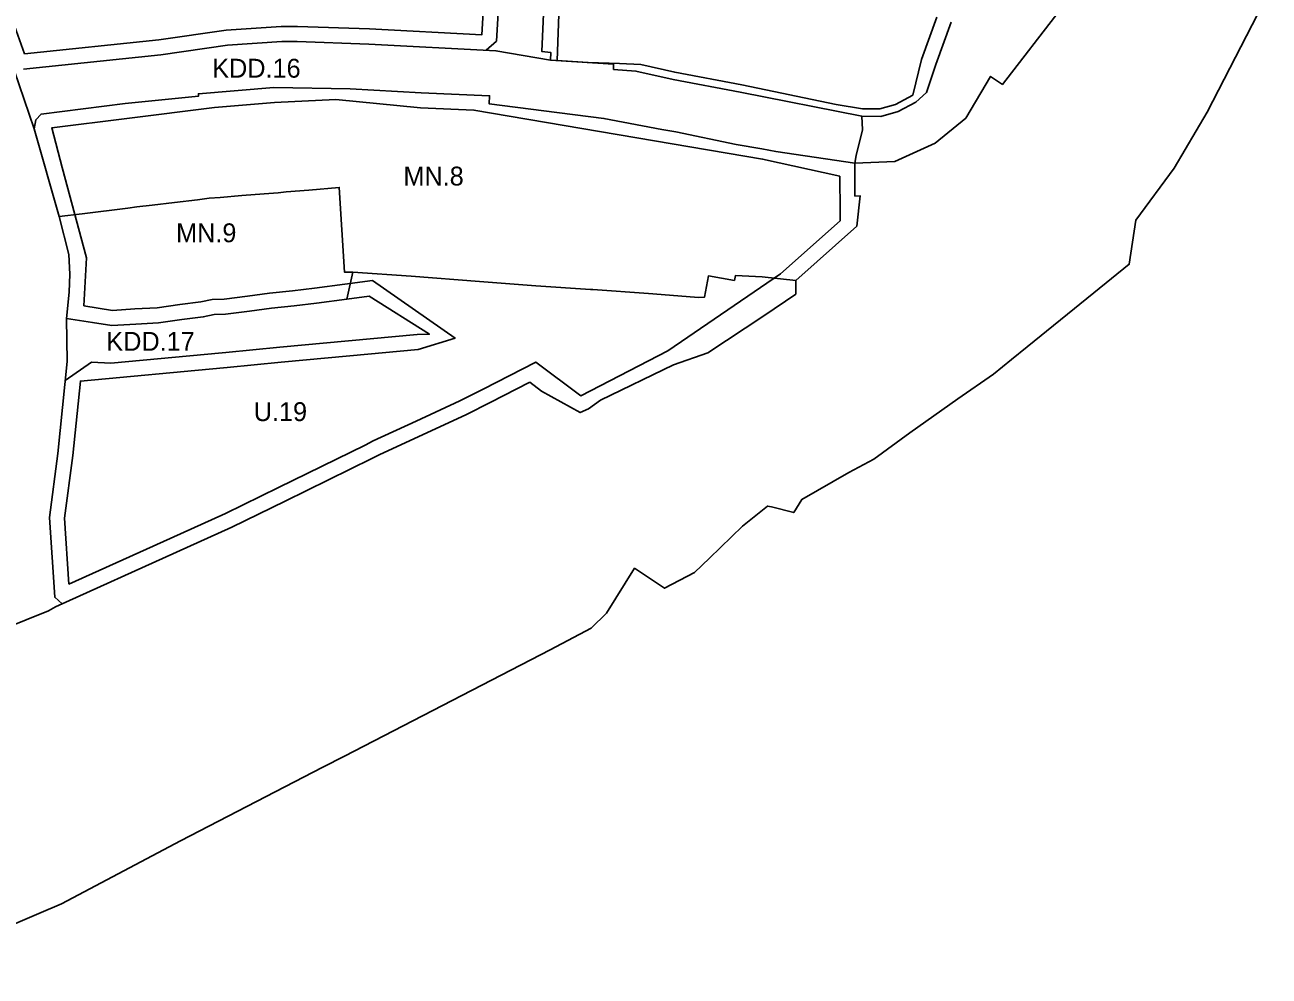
# Model space of a CAD drawing. Extents: x 7428112 to 7429828, y 5548245 to 5549272.
# Drawn here: x 7429274.1 to 7429603.6, y 5548527.3 to 5548779.3 of the extents above; entities that cross this region are included whole.
import ezdxf

# ---------------------------------------------------------------- set-up
doc = ezdxf.new("R2010")
doc.units = 0
for name, color, linetype in [('LIN_granica_planu', 7, 'Continuous'), ('LIN_Linia Zabudowy Nieprzekraczalna', 7, 'Continuous'), ('LIN_linie_rozgraniczajace', 7, 'Continuous'), ('TXT_oznaczenia_przeznaczen', 7, 'Continuous')]:
    doc.layers.add(name, color=color, linetype=linetype)

msp = doc.modelspace()

# ---------------------------------------------------------------- linework, layer by layer
at = {"layer": 'LIN_granica_planu'}
msp.add_lwpolyline([(7429603.57, 5548788.13), (7429587.19, 5548756.2), (7429578.44, 5548741.37), (7429568.31, 5548727.53), (7429566.55, 5548715.89), (7429557.13, 5548708.28), (7429539.53, 5548694.02), (7429535.37, 5548690.64), (7429530.55, 5548686.75), (7429521.17, 5548680.28), (7429508.44, 5548671.21), (7429498.89, 5548664.28), (7429492.28, 5548660.74), (7429479.85, 5548653.6), (7429477.69, 5548650.08), (7429471.8, 5548651.58), (7429470.74, 5548651.84), (7429464.08, 5548646.5), (7429455.39, 5548637.98), (7429451.43, 5548634.24), (7429443.49, 5548630.06), (7429435.54, 5548635.33), (7429428.09, 5548623.47), (7429424.02, 5548619.52), (7429413.15, 5548613.7), (7429358.69, 5548585.55), (7429353, 5548582.61), (7429315.25, 5548563.12), (7429315.25, 5548563.12), (7429283.8, 5548546.45), (7429277.79, 5548543.89), (7429238.95, 5548527.29)], dxfattribs=at)
at = {"layer": 'LIN_Linia Zabudowy Nieprzekraczalna'}
for points in [[(7429273.99, 5548771.63), (7429309.58, 5548775.34), (7429327.36, 5548777.91), (7429341.97, 5548778.88), (7429346.25, 5548778.91), (7429365.33, 5548778.23), (7429395.07, 5548776.65), (7429395.94, 5548791.78), (7429396.25, 5548798.38), (7429396.88, 5548810.65), (7429398.13, 5548829.54), (7429398.89, 5548843.94), (7429359.73, 5548846.77), (7429348.57, 5548847.59), (7429341.93, 5548845.59), (7429332.58, 5548841.75), (7429312.81, 5548833.85), (7429290.54, 5548825.46), (7429258.77, 5548813.12), (7429269.98, 5548782.77), (7429273.99, 5548771.63)], [(7429415.84, 5548791.95), (7429415.06, 5548769.88), (7429423.24, 5548769.35), (7429431.55, 5548769.1), (7429437.18, 5548768.82), (7429446.17, 5548766.76), (7429463.91, 5548763.41), (7429488.93, 5548758.22), (7429495.89, 5548757.09), (7429500.46, 5548757.03), (7429504.59, 5548758.22), (7429509.22, 5548760.7), (7429511.55, 5548770.13), (7429515.58, 5548781.39)], [(7429285.76, 5548631.12), (7429312.55, 5548643.25), (7429327.21, 5548649.89), (7429341.22, 5548656.74), (7429364.19, 5548668), (7429366.28, 5548669.1), (7429377.69, 5548674.35), (7429389.27, 5548679.68), (7429395.47, 5548682.8), (7429409.36, 5548689.98), (7429421.33, 5548681.06), (7429444.35, 5548692.92), (7429474.19, 5548713.38), (7429489.94, 5548727.43), (7429489.94, 5548729.85), (7429489.85, 5548739.22), (7429469.45, 5548743.75), (7429393.01, 5548756.72), (7429378.85, 5548757.31), (7429356.46, 5548759.58), (7429340.17, 5548758.73), (7429324.3, 5548757.39), (7429301.11, 5548754.53), (7429281.21, 5548752.02), (7429283.92, 5548741.49), (7429290.38, 5548717.55), (7429289.71, 5548704.91), (7429297.31, 5548703.65), (7429303.2, 5548704.04), (7429309.08, 5548704.38), (7429315.1, 5548705.2), (7429320.65, 5548705.9), (7429323.69, 5548706.54), (7429326.87, 5548706.66), (7429333.04, 5548707.41), (7429338.9, 5548708.21), (7429344.94, 5548708.83), (7429350.82, 5548709.56), (7429358.81, 5548710.64), (7429366.16, 5548711.56), (7429388.01, 5548696.33), (7429378.19, 5548693.29), (7429360.15, 5548691.63), (7429341.98, 5548689.95), (7429327.65, 5548688.53), (7429326.69, 5548688.44), (7429288.8, 5548684.95), (7429286.81, 5548665.25), (7429284.58, 5548648.66), (7429285.76, 5548631.12)]]:
    msp.add_lwpolyline(points, dxfattribs=at)
at = {"layer": 'LIN_linie_rozgraniczajace'}
for points in [[(7429399.93, 5548791.57), (7429398.98, 5548775.04), (7429396.26, 5548772.58)], [(7429413.24, 5548769.99), (7429413.33, 5548772.01), (7429410.96, 5548772.3), (7429411.85, 5548792.19)], [(7429238.95, 5548527.29), (7429277.79, 5548543.89), (7429283.8, 5548546.45), (7429315.25, 5548563.12), (7429353, 5548582.61), (7429358.69, 5548585.55), (7429413.15, 5548613.7), (7429424.02, 5548619.52), (7429428.09, 5548623.47), (7429435.54, 5548635.33), (7429443.49, 5548630.06), (7429451.43, 5548634.24), (7429455.39, 5548637.98), (7429464.08, 5548646.5), (7429470.74, 5548651.84), (7429471.8, 5548651.58), (7429477.69, 5548650.08), (7429479.85, 5548653.6), (7429492.28, 5548660.74), (7429498.89, 5548664.28), (7429508.44, 5548671.21), (7429521.17, 5548680.28), (7429530.55, 5548686.75), (7429535.37, 5548690.64), (7429539.53, 5548694.02), (7429557.13, 5548708.28), (7429566.55, 5548715.89), (7429568.31, 5548727.53), (7429578.44, 5548741.37), (7429587.19, 5548756.2), (7429603.57, 5548788.13)], [(7429548.21, 5548783.26), (7429532.94, 5548763.53), (7429529.79, 5548765.67), (7429523.23, 5548754.6), (7429515.16, 5548747.95), (7429504.43, 5548743.12), (7429493.82, 5548742.67), (7429493.9, 5548733.96), (7429495.31, 5548734), (7429494.35, 5548726), (7429478.22, 5548711.61), (7429478.28, 5548707.97), (7429469.74, 5548702.26), (7429454.97, 5548692.38), (7429445.88, 5548689.22), (7429426.48, 5548679.91), (7429423.35, 5548677.58), (7429421.17, 5548676.58), (7429410.86, 5548682.29), (7429407.83, 5548684.69)], [(7429519.33, 5548780), (7429515.33, 5548768.81), (7429512.81, 5548761.43), (7429510.03, 5548758.86), (7429505.35, 5548756.36), (7429500.73, 5548755.03), (7429495.68, 5548755.09), (7429463.53, 5548761.45), (7429445.76, 5548764.8), (7429435.89, 5548767.07), (7429430, 5548767.5), (7429430, 5548768.91), (7429413.24, 5548769.99), (7429398.84, 5548772.44), (7429365.15, 5548774.23), (7429346.19, 5548774.91), (7429342.12, 5548774.88), (7429327.78, 5548773.93), (7429310.07, 5548771.37), (7429273.68, 5548767.58)], [(7429283.12, 5548728.5), (7429276.58, 5548751.73), (7429271.29, 5548767.33)], [(7429276.58, 5548751.73), (7429277, 5548754.13), (7429278.39, 5548755.69), (7429300.66, 5548758.51), (7429320.09, 5548760.44), (7429320.05, 5548761.05), (7429340.04, 5548762.73), (7429360.23, 5548762.38), (7429379.05, 5548761.31), (7429397.12, 5548760.55), (7429397.06, 5548758.36), (7429411.52, 5548756.58), (7429427.43, 5548754.52), (7429442.72, 5548751.6), (7429446.5, 5548750.97), (7429462.48, 5548747.64), (7429469.22, 5548746.45), (7429472.9, 5548745.8), (7429493.82, 5548742.67)], [(7429495.68, 5548755.09), (7429495.86, 5548751.53), (7429494.2, 5548744.69), (7429493.82, 5548742.67)], [(7429359.33, 5548706.67), (7429360.89, 5548713.79), (7429358.72, 5548713.81), (7429357.35, 5548736.25), (7429349.27, 5548735.51), (7429343.3, 5548735.04), (7429341.19, 5548734.83), (7429337.45, 5548734.58), (7429331.56, 5548734.09), (7429325.76, 5548733.62), (7429322.87, 5548733.38), (7429319.79, 5548732.97), (7429313.72, 5548732.29), (7429307.8, 5548731.52), (7429303.71, 5548731.11), (7429301.39, 5548730.76), (7429289.28, 5548729.27), (7429283.12, 5548728.5)], [(7429283.12, 5548728.5), (7429285.7, 5548718.45), (7429285.99, 5548713.28), (7429285.83, 5548708.54), (7429285.13, 5548701.48), (7429285.31, 5548690.15), (7429282.84, 5548665.72), (7429280.56, 5548648.79), (7429281.98, 5548627.68), (7429283.97, 5548625.91)], [(7429360.89, 5548713.79), (7429376.42, 5548712.74), (7429394.45, 5548711.31), (7429409.38, 5548710.21), (7429423.85, 5548709.24), (7429424.5, 5548709.17), (7429439.2, 5548708.12), (7429442.54, 5548707.86), (7429452.49, 5548707.04), (7429454.04, 5548707.16), (7429455.11, 5548712.81), (7429461.96, 5548711.62), (7429462.23, 5548712.9), (7429469.32, 5548712.6), (7429478.22, 5548711.61)], [(7429285.13, 5548701.48), (7429291.97, 5548700.48), (7429297.11, 5548699.63), (7429303.45, 5548700.05), (7429309.46, 5548700.4), (7429315.62, 5548701.23), (7429321.32, 5548701.95), (7429324.18, 5548702.56), (7429327.18, 5548702.67), (7429333.55, 5548703.44), (7429339.38, 5548704.24), (7429345.39, 5548704.86), (7429351.33, 5548705.59), (7429359.33, 5548706.67), (7429365.24, 5548707.41), (7429381.22, 5548697.35), (7429377.97, 5548697.29), (7429359.78, 5548695.61), (7429341.6, 5548693.93), (7429327.26, 5548692.51), (7429326.32, 5548692.42), (7429296.86, 5548689.71), (7429291.73, 5548689.91), (7429284.79, 5548685.05)], [(7429407.83, 5548684.69), (7429397.29, 5548679.24), (7429391.01, 5548676.08), (7429379.36, 5548670.72), (7429368.05, 5548665.51), (7429366, 5548664.43), (7429342.98, 5548653.15), (7429328.91, 5548646.27), (7429314.2, 5548639.61), (7429282.15, 5548625.09), (7429280.37, 5548624.1), (7429256.15, 5548614.36)]]:
    msp.add_lwpolyline(points, dxfattribs=at)

# ---------------------------------------------------------------- texts
at = {"layer": 'TXT_oznaczenia_przeznaczen'}
for s, p in [('KDD.16', (7429323.69, 5548765.33)), ('MN.8', (7429374.32, 5548736.75)), ('MN.9', (7429314.12, 5548721.72)), ('KDD.17', (7429295.66, 5548692.97)), ('U.19', (7429334.69, 5548674.34))]:
    msp.add_text(s, height=5, dxfattribs=at).set_placement(p)

doc.saveas('drawing.dxf')
